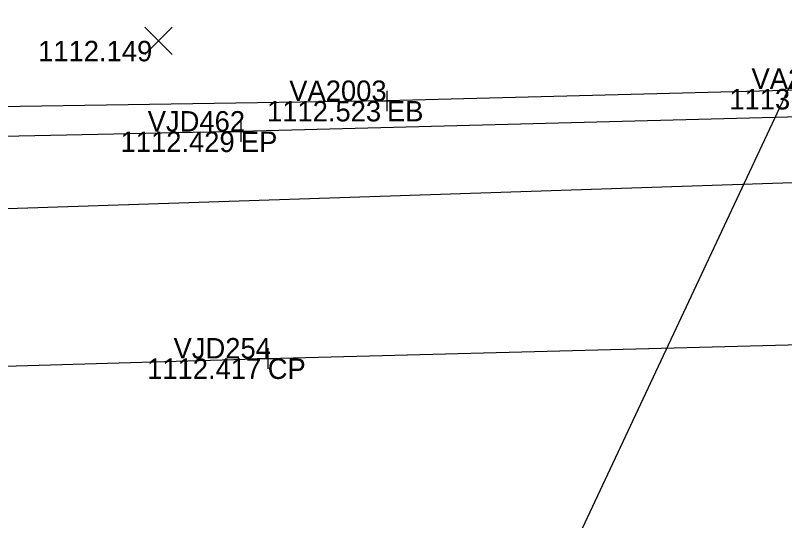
# Model space of a CAD drawing. Extents: x 1629915 to 1630675, y 484401 to 484601.
# Drawn here: x 1630516.9 to 1630554.5, y 484489.53 to 484514.24 of the extents above; entities that cross this region are included whole.
import ezdxf

# ---------------------------------------------------------------- set-up
doc = ezdxf.new("R2010")
doc.units = 0
for name, color, linetype in [('BR_X_Sub_Foot_Object', 7, 'Continuous'), ('PV_X_COP', 7, 'Continuous'), ('PV_X_EOP', 7, 'Continuous'), ('PV_X_Shoulder_Aggregate', 7, 'Continuous'), ('SV_X_Random_Point', 7, 'Continuous'), ('SV_X_Shot_Marker', 7, 'Continuous'), ('SV_X_Text_Comment', 7, 'Continuous'), ('SV_X_Text_Elevation', 7, 'Continuous'), ('SV_X_Text_Name', 7, 'Continuous'), ('UT_X_Sanitary_Line', 7, 'Continuous')]:
    doc.layers.add(name, color=color, linetype=linetype)

msp = doc.modelspace()

# ---------------------------------------------------------------- linework, layer by layer
at = {"layer": 'BR_X_Sub_Foot_Object'}
msp.add_line((1630537.673, 484474.324), (1630560.47, 484522.988), dxfattribs=at)
at = {"layer": 'PV_X_COP'}
msp.add_lwpolyline([(1630297.366, 484489.973), (1630308.553, 484490.492), (1630361.839, 484492.402), (1630403.565, 484493.662), (1630440.464, 484494.931), (1630486.149, 484496.207), (1630529.234, 484497.459), (1630568.325, 484498.484), (1630611.926, 484499.834), (1630649.713, 484500.97)], dxfattribs=at)
at = {"layer": 'PV_X_EOP'}
msp.add_lwpolyline([(1630649.544, 484512.337), (1630611.095, 484510.961), (1630568.311, 484509.618), (1630527.921, 484508.555), (1630486.049, 484507.685), (1630439.965, 484506.412), (1630403.104, 484505.478), (1630361.875, 484504.434), (1630301.74, 484502.192)], dxfattribs=at)
at = {"layer": 'PV_X_Shoulder_Aggregate'}
msp.add_lwpolyline([(1630609.295, 484512.622), (1630601.375, 484512.79), (1630594.371, 484513.028), (1630564.661, 484511.714), (1630557.668, 484510.64), (1630535.062, 484510.052), (1630513.96, 484509.735), (1630489.956, 484510.39), (1630468.462, 484511.02), (1630445.091, 484511.198), (1630420.706, 484511.45), (1630393.49, 484511.943), (1630369.145, 484512.288), (1630344.7, 484511.845), (1630320.659, 484510.608), (1630304.125, 484509.436), (1630303.965, 484508.981)], dxfattribs=at)
at = {"layer": 'SV_X_Random_Point'}
for p, q in [((1630523.226, 484512.323), (1630524.559, 484513.658)), ((1630523.226, 484513.658), (1630524.559, 484512.323))]:
    msp.add_line(p, q, dxfattribs=at)
at = {"layer": 'SV_X_Shot_Marker'}
for p, q in [((1630535.062, 484510.552), (1630535.062, 484509.552)), ((1630534.562, 484510.052), (1630535.562, 484510.052)), ((1630535.062, 484510.052), (1630535.062, 484510.052)), ((1630527.921, 484509.055), (1630527.921, 484508.055)), ((1630527.421, 484508.555), (1630528.421, 484508.555)), ((1630527.921, 484508.555), (1630527.921, 484508.555)), ((1630529.234, 484497.959), (1630529.234, 484496.959)), ((1630528.734, 484497.459), (1630529.734, 484497.459)), ((1630529.234, 484497.459), (1630529.234, 484497.459))]:
    msp.add_line(p, q, dxfattribs=at)
at = {"layer": 'UT_X_Sanitary_Line'}
msp.add_lwpolyline([(1629930.746, 484483.734), (1630048.132, 484488.308), (1630252.717, 484494.605), (1630261.76, 484567.793), (1630373.422, 484500.095), (1630654.857, 484509.349)], dxfattribs=at)

# ---------------------------------------------------------------- texts
at = {"layer": 'SV_X_Text_Comment'}
for s, p in [('EB', (1630535.062, 484509.052)), ('EP', (1630527.921, 484507.555)), ('CP', (1630529.234, 484496.459))]:
    msp.add_text(s, height=1, dxfattribs=at).set_placement(p)
at = {"layer": 'SV_X_Text_Elevation'}
for s, p in [('1112.149', (1630518.011, 484511.991)), ('1113.385', (1630551.799, 484509.64)), ('1112.523', (1630529.2, 484509.052)), ('1112.429', (1630522.04, 484507.555)), ('1112.417', (1630523.34, 484496.459))]:
    msp.add_text(s, height=1, dxfattribs=at).set_placement(p)
at = {"layer": 'SV_X_Text_Name'}
for s, p in [('VA2002', (1630552.884, 484510.64)), ('VA2003', (1630530.287, 484510.052)), ('VJD462', (1630523.368, 484508.555)), ('VJD254', (1630524.632, 484497.459))]:
    msp.add_text(s, height=1, dxfattribs=at).set_placement(p)

doc.saveas('drawing.dxf')
